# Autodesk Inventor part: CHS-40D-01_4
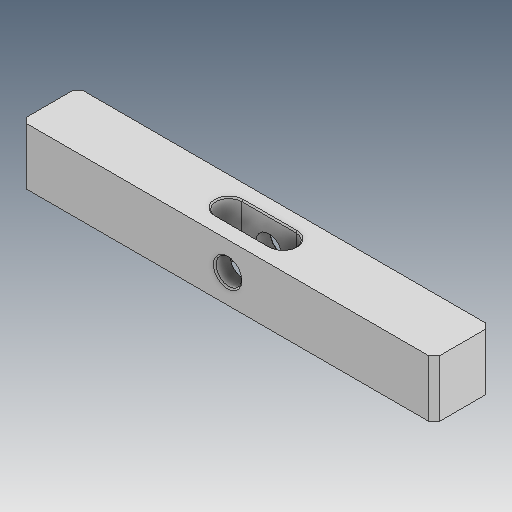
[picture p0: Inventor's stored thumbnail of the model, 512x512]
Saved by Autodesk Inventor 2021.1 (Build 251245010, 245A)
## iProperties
Created: 2019-04
Part Number: CHS-40D-01_4
Material: Ogólny
Document SubType Name: Modeling
Designer: user
Density: 1 g/cm^3
Appearance: Domyślna
Author: user
Revision Number: ÈÎºÎ
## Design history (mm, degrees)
feature "ÊäÈë1"
node "Bryła1"
